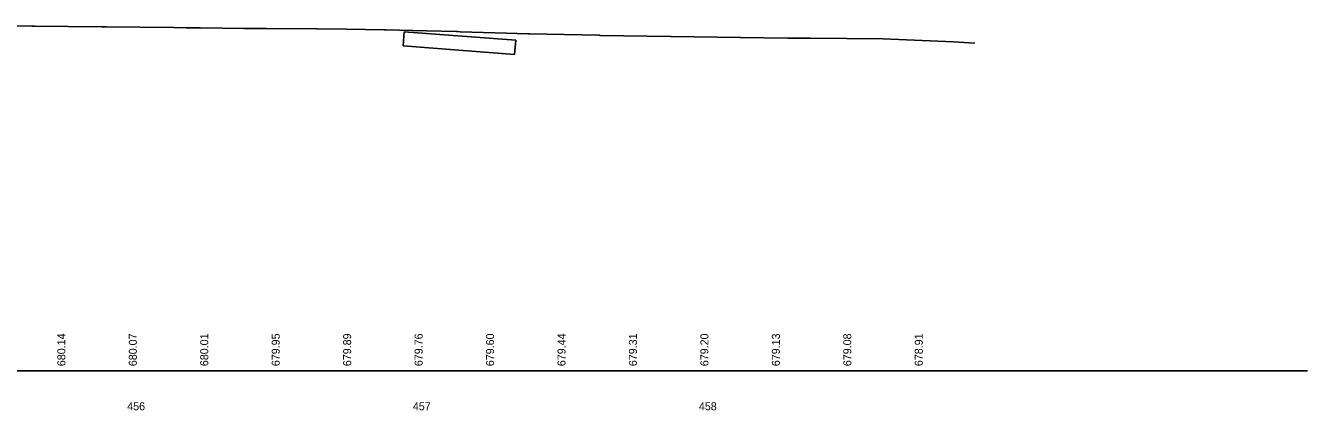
# Model space of a CAD drawing. Extents: x 157201 to 163282, y 424960 to 427200.
# Drawn here: x 162167.4 to 162615.9, y 425949.5 to 426084.2 of the extents above; entities that cross this region are included whole.
import ezdxf

# ---------------------------------------------------------------- set-up
doc = ezdxf.new("R2010")
doc.units = 0
for name, color, linetype in [('DR_X_Elev_Flow', 7, 'Continuous'), ('RD_X_Fence', 7, 'Continuous'), ('RD_X_GR_Rt', 7, 'Continuous'), ('SV_X_Shot_Marker', 7, 'Continuous'), ('UT_X_Water_Cells', 7, 'Continuous')]:
    doc.layers.add(name, color=color, linetype=linetype)

msp = doc.modelspace()

# ---------------------------------------------------------------- linework, layer by layer
at = {"layer": 'DR_X_Elev_Flow'}
for p, q in [((162299.83, 426082.08), (162299.45, 426077.09)), ((162299.83, 426082.08), (162338.87, 426079.12)), ((162338.87, 426079.12), (162338.49, 426074.13)), ((162299.45, 426077.09), (162338.49, 426074.13))]:
    msp.add_line(p, q, dxfattribs=at)
at = {"layer": 'SV_X_Shot_Marker'}
msp.add_line((161406.29, 425963.36), (162615.86, 425963.36), dxfattribs=at)
at = {"layer": 'UT_X_Water_Cells'}
msp.add_lwpolyline([(162145.11, 426084.23), (162169.53, 426084.06), (162169.54, 426084.06), (162170.65, 426084.04), (162194.04, 426083.77), (162194.32, 426083.77), (162194.59, 426083.77), (162195.61, 426083.76), (162219.3, 426083.53), (162223.61, 426083.49), (162228.56, 426083.43), (162243.72, 426083.24), (162244.03, 426083.24), (162251.62, 426083.2), (162269.12, 426083.1), (162269.37, 426083.1), (162279.62, 426082.93), (162292.82, 426082.71), (162293.28, 426082.7), (162293.42, 426082.7), (162307.63, 426082.37), (162318, 426082.13), (162318.61, 426082.11), (162319.41, 426082.1), (162335.63, 426081.62), (162343.15, 426081.4), (162343.66, 426081.39), (162368.04, 426080.83), (162368.45, 426080.82), (162393.06, 426080.38), (162393.27, 426080.37), (162417.44, 426080.01), (162417.64, 426080.01), (162434.12, 426079.87), (162441.87, 426079.8), (162441.95, 426079.8), (162467.4, 426079.59), (162467.41, 426079.59), (162492.02, 426078.52), (162499.46, 426078.1)], dxfattribs=at)

# ---------------------------------------------------------------- texts
at = {"layer": 'RD_X_Fence'}
for s, p in [('680.14', (162181.29, 425964.97)), ('680.07', (162206.29, 425964.97)), ('680.01', (162231.29, 425964.97)), ('679.95', (162256.29, 425964.97)), ('679.89', (162281.29, 425964.97)), ('679.76', (162306.29, 425964.97)), ('679.60', (162331.29, 425964.97)), ('679.44', (162356.29, 425964.97)), ('679.31', (162381.29, 425964.97)), ('679.20', (162406.29, 425964.97)), ('679.13', (162431.29, 425964.97)), ('679.08', (162456.29, 425964.97)), ('678.91', (162481.29, 425964.97))]:
    msp.add_text(s, height=2.8, rotation=90, dxfattribs=at).set_placement(p)
at = {"layer": 'RD_X_GR_Rt'}
for s, p in [('456', (162202.93, 425949.52)), ('457', (162302.87, 425949.52)), ('458', (162402.96, 425949.52))]:
    msp.add_text(s, height=2.8, dxfattribs=at).set_placement(p)

doc.saveas('drawing.dxf')
